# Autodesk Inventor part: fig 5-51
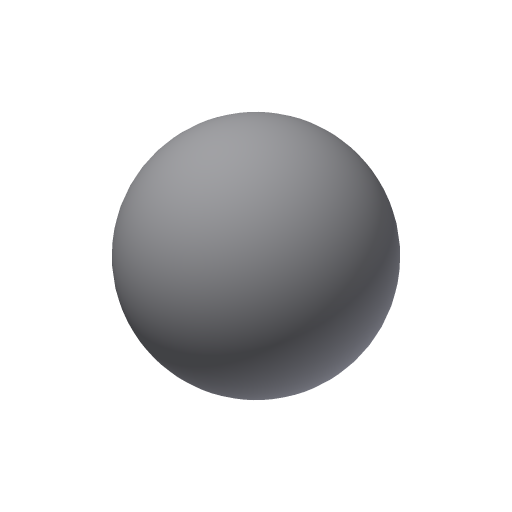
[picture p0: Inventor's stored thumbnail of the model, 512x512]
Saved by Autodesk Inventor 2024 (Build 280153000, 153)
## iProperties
Created: 2012-07
Part Number: fig 5-51
Material: Generic
Document SubType Name: Modeling
Designer: CADCIM
Density: 1 g/cm^3
Appearance: Default
Author: CADCIM
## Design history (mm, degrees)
sketch "Sketch1"
  geometry: L1 (7.807, -5.174)-(-7.807, 5.174); A1 r 9.366 centre (0, 0) between (7.807, -5.174) and (-7.807, 5.174)
  constraints: 2 end point, 2 point on circle, 1 centre point, 1 midpoint
revolve "Revolution1" sketch "Sketch1" stored, may be unused: angle "d0" = 90 deg
workpoint "Work Point1"
body "Solid1"
